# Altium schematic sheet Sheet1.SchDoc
size B; SheetNumber: 1; SheetTotal: 1; SPICEModelCacheKHWKRCUS: <root> / <DocumentId>KHWKRCUS</DocumentId> / <CacheFrame Number="0"> / <Model Name="nmos" Kind="MDL"> / <Text>*Default N-Channel MOSFET / *Pinout: D,G,S / .MODEL NMOS NMOS()</Text> / </Model> / <Model Name="diode" Kind="MDL"> / <Text>*Default Diode / *Diode Pinout: A,K / .MODEL DIODE D()</Text> / </Model> / </CacheFrame> / </root>
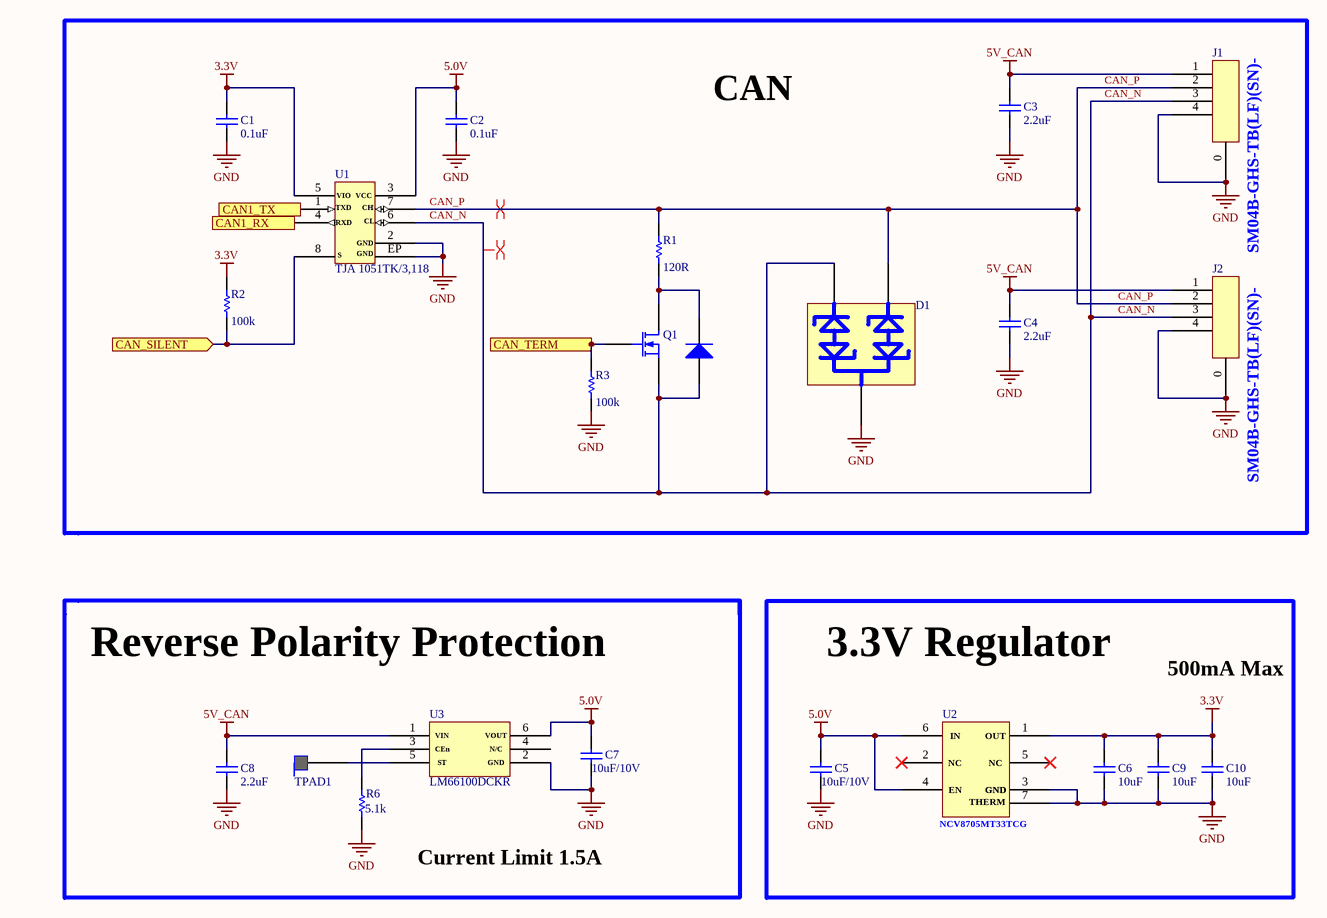
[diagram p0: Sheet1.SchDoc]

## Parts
C1  0.1uF  [RAD-0.3]
C2  0.1uF  [RAD-0.3]
C3  2.2uF  [RAD-0.3]
C4  2.2uF  [RAD-0.3]
C5  10uF/10V  [RAD-0.3]
C6  10uF  [RAD-0.3]
C7  10uF/10V  [RAD-0.3]
C8  2.2uF  [RAD-0.3]
C9  10uF  [RAD-0.3]
C10  10uF  [RAD-0.3]
D1  BRIDGE  (value not drawn)
D?  Diode  [SMC]  (value not drawn)
J1  HEADER  (value not drawn)
J2  HEADER  (value not drawn)
Q1  MOSFET-N  [E3]  (value not drawn)
R1  120R  [AXIAL-0.3]
R2  100k  [AXIAL-0.3]
R3  100k  [AXIAL-0.3]
R6  5.1k  [AXIAL-0.3]
TPAD1  TPAD  (value not drawn)
U1  TJA 1051TK/3,118
U2  NCV8705MT33TCG  (value not drawn)
U3  LM66100DCKR

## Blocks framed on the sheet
3.3V Regulator: C5 C6 C9 C10 U2

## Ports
CAN1_RX (out), CAN1_TX (in), CAN_SILENT (in), CAN_TERM (in)

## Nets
3.3V: C1.2 C6.2 C9.2 C10.2 R2.2 U1.5 U2.1
5.0V: C2.2 C5.2 C7.2 U1.3 U2.4 U2.6 U3.6
5V_CAN: C3.2 C4.2 C8.2 J1.1 J2.1 U3.1
GND: C1.1 C2.1 C3.1 C4.1 C5.1 C6.1 C7.1 C8.1 C9.1 C10.1 D1.3 J1.0 J1.4 J2.0 J2.4 R3.1 R6.1 U1.2 U1.EP U2.3 U2.7 U3.2
CAN1_RX: U1.4 ; port CAN1_RX
CAN_N: D1.2 D?.1(A) J1.3 J2.3 Q1.3(S) U1.6
CAN_P: D1.1 J1.2 J2.2 R1.2 U1.7
CAN_SILENT: R2.1 U1.8 ; port CAN_SILENT
CAN_TERM: Q1.2(G) R3.2 ; port CAN_TERM
NetD?_2: D?.2(K) Q1.1(D) R1.1
NetR6_2: R6.2 U3.3
NetTPAD1_1: TPAD1.1 U3.5

Not connected (* = marked no-connect by the designer): U1 1; U2 2* 5*; U3 4

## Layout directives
differential pair: CAN_N, CAN_P

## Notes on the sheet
- CAN
- (near J1) SM04B-GHS-TB(LF)(SN)-
- (near J2) SM04B-GHS-TB(LF)(SN)-
- Reverse Polarity Protection
- 500mA Max
- Current Limit 1.5A
- (near U2) NCV8705MT33TCG

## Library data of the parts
C1-C10 = Cap: Capacitor
D? = Diode: Default Diode
Q1 = MOSFET-N: N-Channel MOSFET
R1-R3 R6 = Res1: Resistor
